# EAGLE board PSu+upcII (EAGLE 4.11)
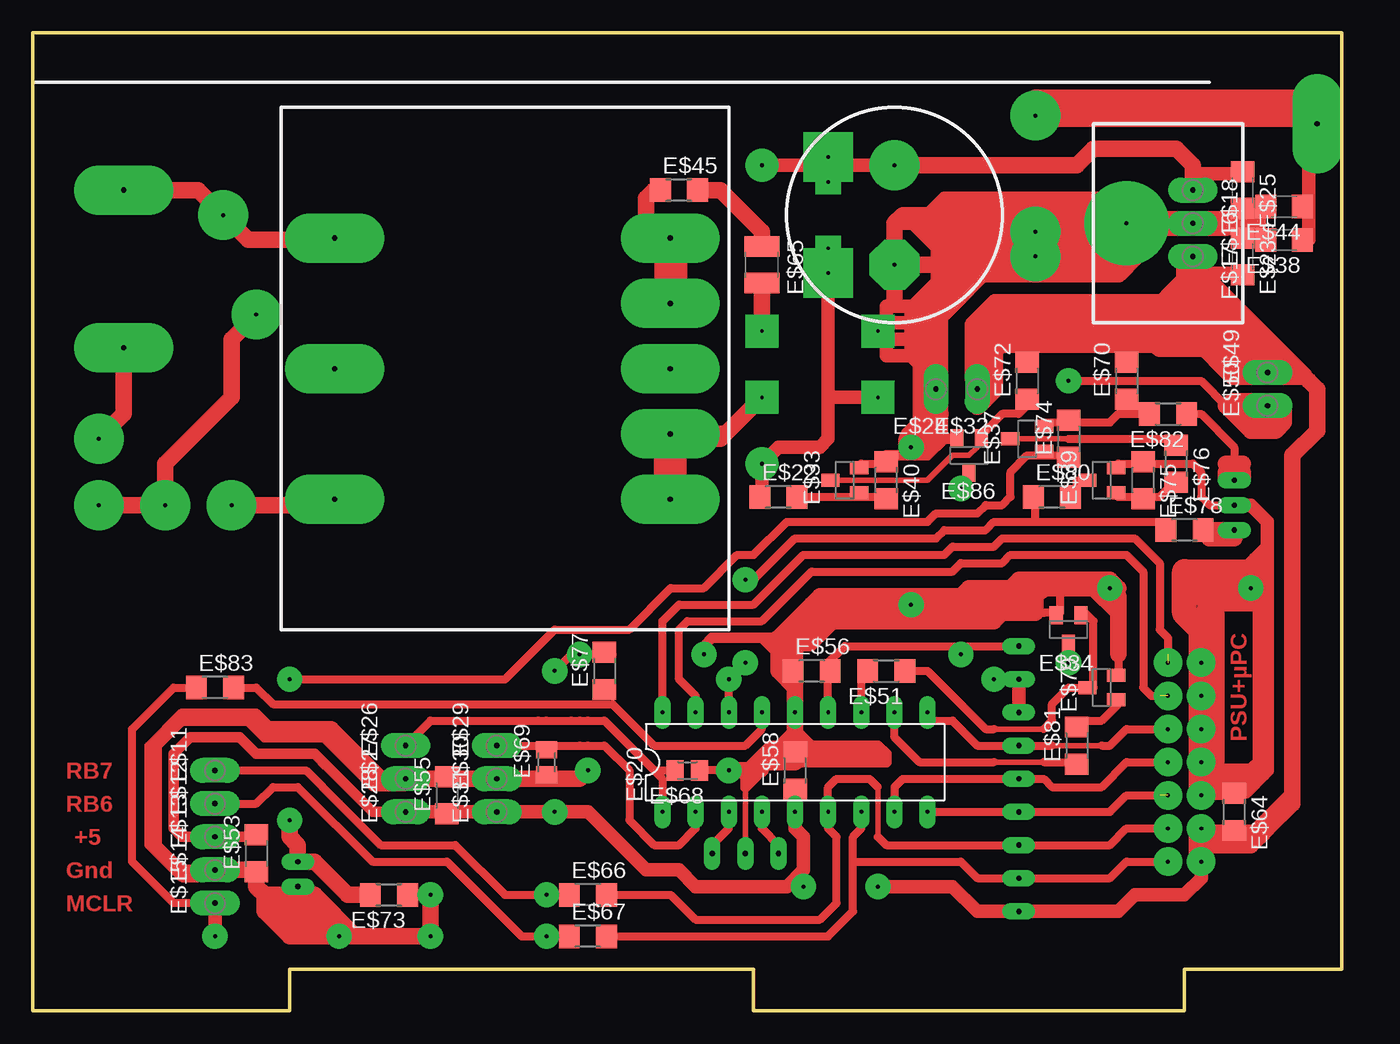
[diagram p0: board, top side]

Size 100.33 x 74.93 mm. Coordinates in mm from the lower left corner, seen from the top.
Outline: 0,0 19.68,0 19.68,3.17 55.24,3.17 55.24,0 88.27,0 88.27,3.17 100.33,3.17 100.33,74.93 0,74.93 0,0
Copper layers (1*16): Top 0.035mm / dielectric 1.5mm / Bottom 0.035mm
Design rules "default": minimum track width 10mil, minimum drill 24mil, track to track 8mil, track to pad 8mil, pad to pad 8mil, via to via 8mil, smd to smd 8mil, copper to edge 40mil, drill to drill 8mil, minimum pad ring 10mil, minimum via ring 8mil, stop-mask expansion 4mil, vias tented up to drill 0mil, thermal gap 10mil

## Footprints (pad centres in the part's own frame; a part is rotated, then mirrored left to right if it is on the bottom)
EC3,81 = drill 0.406 pad 3.81 long: P$1 0,0
P1-13Y = drill 0.406 pad 1.905 long: 1 0,0
DIL18 = drill 0.305 pad 1.27 long: 1 -10.16,-3.81; 2 -7.62,-3.81; 3 -5.08,-3.81; 4 -2.54,-3.81; 5 0,-3.81; 6 2.54,-3.81; 7 5.08,-3.81; 8 7.62,-3.81; 9 10.16,-3.81; 10 10.16,3.81; 11 7.62,3.81; 12 5.08,3.81; 13 2.54,3.81; 14 0,3.81; 15 -2.54,3.81; 16 -5.08,3.81; 17 -7.62,3.81; 18 -10.16,3.81
EC1,27 = drill 0.406 pad 1.27 long: P$1 0,0
R1206 = smd 1.6 x 1.803: 1 -1.422,0; 2 1.422,0
C1206 = smd 1.6 x 1.8: 1 -1.4,0; 2 1.4,0
SOT23 = smd 1 x 1.4: 1 -0.95,-1.1; 2 0.95,-1.1; 3 0,1.1
SOT23W = smd 1 x 1.4: 1 -0.95,-1.303; 3 0.95,-1.303; 4 0,1.303
C1210 = smd 1.6 x 2.7: 1 -1.4,0; 2 1.4,0
M0805 = smd 1.3 x 1.6: 1 -0.95,0; 2 0.95,0

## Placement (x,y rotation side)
E$1  [EC3,81]  23.14,59.19 90 top
E$2  [EC3,81]  6.99,50.8 90 top
E$3  [EC3,81]  23.14,39.19 90 top
E$4  [EC3,81]  6.99,62.87 90 top
E$5  [EC3,81]  48.85,59.19 90 top
E$6  [EC3,81]  48.85,54.19 90 top
E$7  [EC3,81]  48.85,49.19 90 top
E$8  [EC3,81]  48.85,44.19 90 top
E$9  [EC3,81]  48.85,39.19 90 top
E$10  [EC3,81]  23.14,49.19 90 top
E$11  [P1-13Y]  13.97,18.41 90 top
E$12  [P1-13Y]  13.97,15.88 90 top
E$13  [P1-13Y]  13.97,13.34 90 top
E$14  [P1-13Y]  13.97,10.79 90 top
E$15  [P1-13Y]  13.97,8.26 90 top
E$16  [P1-13Y]  88.9,60.33 270 top
E$17  [P1-13Y]  88.9,57.78 270 top
E$18  [P1-13Y]  88.9,62.87 270 top
E$19  [EC3,81]  98.42,67.94 0 top
E$20  [DIL18]  58.42,19.05 0 top
E$21  [EC1,27]  75.56,25.4 270 top
E$22  [R1206]  57.15,39.37 0 top
E$23  [C1206]  92.71,57.78 270 top
E$24  [P1-13Y]  69.22,47.62 180 top
E$25  [C1206]  92.71,62.87 270 top
E$26  [P1-13Y]  28.57,20.32 90 top
E$27  [P1-13Y]  28.57,17.78 90 top
E$28  [P1-13Y]  28.57,15.24 90 top
E$29  [P1-13Y]  35.56,20.32 90 top
E$30  [P1-13Y]  35.56,17.78 90 top
E$31  [P1-13Y]  35.56,15.24 90 top
E$32  [P1-13Y]  72.39,47.62 180 top
E$33  [SOT23]  62.23,40.64 90 top
E$34  [SOT23]  79.38,29.21 180 top
E$35  [EC1,27]  20.32,9.53 270 top
E$36  [EC1,27]  20.32,11.43 270 top
E$37  [SOT23W]  76.2,43.81 90 top
E$38  [C1206]  95.89,59.05 180 top
E$39  [SOT23]  81.92,40.64 90 top
E$40  [R1206]  65.41,40.64 270 top
E$41  [EC1,27]  57.15,12.06 180 top
E$42  [EC1,27]  54.61,12.06 180 top
E$43  [EC1,27]  52.07,12.06 180 top
E$44  [C1206]  95.89,61.59 180 top
E$45  [R1206]  49.53,62.87 0 top
E$46  [EC1,27]  92.08,36.83 90 top
E$47  [EC1,27]  92.08,38.73 90 top
E$48  [EC1,27]  92.08,40.64 90 top
E$49  [P1-13Y]  94.61,48.9 90 top
E$50  [P1-13Y]  94.61,46.35 90 top
E$51  [R1206]  65.41,26.04 180 top
E$52  [EC1,27]  75.56,22.86 270 top
E$53  [R1206]  17.14,12.06 90 top
E$54  [EC1,27]  75.56,20.32 270 top
E$55  [R1206]  31.75,16.51 90 top
E$56  [R1206]  59.69,26.04 0 top
E$57  [EC1,27]  75.56,17.78 270 top
E$58  [R1206]  58.42,18.41 90 top
E$59  [EC1,27]  75.56,15.24 270 top
E$60  [EC1,27]  75.56,12.7 270 top
E$61  [EC1,27]  75.56,10.16 270 top
E$62  [EC1,27]  75.56,27.94 270 top
E$63  [EC1,27]  75.56,7.62 270 top
E$64  [R1206]  92.08,15.24 270 top
E$65  [C1210]  55.88,57.15 270 top
E$66  [R1206]  42.55,8.89 0 top
E$67  [R1206]  42.55,5.71 0 top
E$68  [M0805]  50.16,18.41 180 top
E$69  [M0805]  39.37,19.05 90 top
E$70  [R1206]  83.82,48.26 90 top
E$72  [R1206]  76.2,48.26 90 top
E$73  [R1206]  27.3,8.89 180 top
E$74  [R1206]  79.38,43.81 90 top
E$75  [R1206]  85.09,40.64 270 top
E$76  [R1206]  87.63,41.91 270 top
E$77  [R1206]  43.81,26.04 90 top
E$78  [R1206]  88.27,36.83 0 top
E$79  [SOT23]  81.92,24.77 90 top
E$80  [R1206]  78.11,39.37 0 top
E$81  [R1206]  80.01,20.32 90 top
E$82  [R1206]  87,45.72 180 top
E$83  [R1206]  13.97,24.77 0 top
E$86  [SOT23W]  71.75,42.55 180 top

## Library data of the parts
E$1-E$10 E$19 E$21 E$35 E$36 E$41-E$43 E$46-E$48 E$52 E$54 E$57 E$59-E$63 = Pads
E$11-E$18 E$24 E$26-E$32 E$49 E$50 = testpad
E$20 = 40xx
E$22 E$23 E$25 E$37 E$38 E$40 E$44 E$45 E$51 E$53 E$55 E$56 E$58 E$64-E$70 E$72-E$78 E$80-E$83 E$86 = smd-ipc
E$33 E$34 E$39 E$79 = transistor-npn

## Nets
S$2: E$2.P$1 E$4.P$1
S$5: E$13.1 E$20.5 E$28.1 E$31.1
S$6: E$18.1
S$25: E$20.7
S$26: E$20.6
S$27: E$20.12
S$29: E$50.1
S$32: E$20.17
S$33: E$20.4
S$34: E$20.3
S$36: E$36.P$1
S$40: E$11.1
S$44: E$17.1 E$49.1
S$45: E$20.2 E$29.1
S$50: E$21.P$1 E$52.P$1
S$54: E$47.P$1
S$57: E$20.13
S$60: E$20.14
S$65: E$12.1
S$66: E$27.1 E$30.1
S$68: E$20.16
S$71: E$20.1 E$26.1
S$75: E$14.1
S$80: E$20.11
S$85: E$48.P$1
S$87: E$15.1
S$88: E$16.1
S$91: E$20.15
S$101: E$46.P$1
S$102: E$20.9

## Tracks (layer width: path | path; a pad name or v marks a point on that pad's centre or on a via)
S$1  (via drill 0.3 pad 3.81)
  Top 1.27: v15.24,38.73 22.86,38.73
S$2  (via drill 0.3 pad 3.81)
  Top 1.27: E$4.P$1 12.7,62.87 v14.61,60.96 16.51,59.05 23.5,59.05 | v5.08,43.81 6.99,45.72 E$2.P$1 | v5.08,38.73 v10.16,38.73 10.16,41.91 15.24,46.99 15.24,51.44 v17.14,53.34
S$3
  Top 0.61: 16.51,22.86 17.78,21.59 18.41,20.95 | 16.51,22.86 11.43,22.86 8.89,20.32 8.89,12.7 11.43,10.16 12.7,10.16 | 16.51,22.86 17.14,22.86 18.41,21.59
  Top 1.27: 27.3,17.78 26.67,17.78 22.86,21.59 18.41,21.59 17.78,21.59
S$4
  Top 1.27: 66.04,54.61 66.04,55.88
S$5
  Top 0.61: E$31.1 41.27,15.24
  Top 0.813: E$31.1 E$28.1 26.04,15.24 22.86,18.41 | 22.86,18.41 22.23,19.05 | 22.86,18.41 21.59,19.68 17.14,19.68 15.88,20.95 12.06,20.95 10.79,19.68 10.79,13.97 11.43,13.34 E$13.1 17.14,13.34
  Top 1.016: E$20.5 58.42,13.97 59.05,13.34 59.05,10.79 57.78,9.53 50.8,9.53 49.53,10.79 46.99,10.79 42.55,15.24 41.27,15.24 | 41.27,15.24 41.91,15.24 | E$28.1 41.27,15.24
S$6  (via drill 0.25 pad 3.81, 0.3 pad 2.54, 0.3 pad 3.81)
  Top 1.016: v60.96,65.41 62.87,64.77 | v55.88,64.77 62.87,64.77 | 62.87,64.77 v66.04,64.77
  Top 1.27: E$18.1 88.9,64.77 87.63,66.04 81.28,66.04 80.01,64.77 v66.04,64.77
S$7
  Top 0.61: 35.56,20.32 36.83,20.32
S$8  (via drill 0.3 pad 1.93)
  other vias: 59.05,9.53
S$9  (via drill 0.25 pad 3.81, 0.3 pad 2.54)
  Top 0.813: 60.33,43.18 58.42,43.18 | 62.23,46.99 64.77,46.99 65.41,46.99
  Top 1.016: 55.88,39.37 v55.88,41.91 57.15,43.18 60.33,43.18 60.96,43.81 60.96,46.99 | 64.77,46.99 60.96,46.99 | 60.96,46.99 v60.96,56.52
S$10  (via drill 0.3 pad 1.93)
  Top 0.61: v54.61,33.02 55.24,33.02 58.42,36.2 69.22,36.2 69.85,36.83 73.03,36.83 73.66,37.47 76.83,37.47 | 76.83,37.47 87,37.47 | 76.83,37.47 76.83,38.73
S$11  (via drill 0.3 pad 1.93, 0.3 pad 2.18)
  Top 1.016: 90.81,32.38 90.81,33.02 | 90.81,32.38 v93.34,32.38 | 90.81,31.75 90.81,32.38 | 90.81,31.75 93.34,31.75 | 90.81,18.41 90.81,17.78 | 90.81,18.41 90.81,31.75 | 93.98,18.41 90.81,18.41
  Top 1.93: 93.98,34.29 93.34,33.66 88.27,33.66 88.27,30.48 89.53,29.21 v89.53,26.67 89.53,17.14 | 93.98,18.41 92.71,17.14 89.53,17.14 | v89.53,16.51 89.53,17.14
S$12
  Top 2.54: 83.82,59.69 76.83,59.69 74.3,57.15
S$13  (via drill 0.25 pad 1.93)
  other vias: 60.96,63.5
S$14
  Top 0.61: 41.27,22.23 42.55,22.23
S$15  (via drill 0.25 pad 1.93)
  other vias: 60.96,58.42
S$16
  Top 0.61: 58.42,39.37 64.77,39.37
S$17  (via drill 0.3 pad 1.93)
  other vias: 40.01,15.24
S$18
  Top 0.61: 63.5,41.91 64.77,41.91
S$19  (via drill 0.3 pad 1.93)
  other vias: 73.66,25.4
S$20
  Top 1.422: 76.83,69.85 98.42,69.85
S$21
  Top 2.54: 48.9,39.37 48.9,43.81
S$22
  Top 1.016: 89.53,64.14 92.71,64.14
S$23  (via drill 0.3 pad 1.93)
  other vias: 71.12,27.3
S$24
  Top 0.61: 83.19,39.37 86.36,39.37 87,40.01
S$25  (via drill 0.3 pad 2.18)
  Top 0.61: v87,11.43 83.82,11.43 82.55,10.16 72.39,10.16 71.12,11.43 62.87,11.43 | E$20.7 63.5,13.97 62.87,13.34 62.87,11.43 | 62.87,11.43 62.87,7.62 60.96,5.71 44.45,5.71
S$26  (via drill 0.3 pad 2.18)
  Top 0.406: 64.77,17.14 64.77,13.34
  Top 0.61: 43.81,8.89 48.9,8.89 50.8,6.99 60.33,6.99 61.59,8.26 61.59,13.34 60.96,13.97 E$20.6 60.96,17.14 61.59,17.78 64.14,17.78 64.77,17.14 | v87,13.97 83.82,13.97 82.55,12.7 65.41,12.7 64.77,13.34
S$27
  Top 0.61: 63.5,24.77 E$20.12 63.5,26.04
S$28
  Top 1.27: 75.56,52.07 76.2,52.07
S$29  (via drill 0.3 pad 1.93)
  Top 0.61: v79.38,48.26 89.53,48.26 91.44,46.35 92.08,46.35
  Top 1.27: 95.89,46.35 95.89,45.09 95.25,44.45 93.34,44.45 91.44,46.35
  Top 1.93: E$50.1 92.71,46.35 | 92.71,46.35 92.08,46.35 | 92.71,46.35 92.71,45.72 93.34,45.09 95.25,45.09 95.25,46.35
S$31  (via drill 0.3 pad 1.93)
  other vias: 71.12,40.01
S$32  (via drill 0.3 pad 2.18)  (1 unrouted)
  Top 0.61: E$20.17 50.8,24.13 49.53,25.4 49.53,29.21 50.16,29.84 55.88,29.84 59.69,33.66 70.48,33.66 71.12,34.29 74.3,34.29 74.93,34.92 83.82,34.92 85.09,33.66 85.09,24.77 85.72,24.13 v87,24.13 | 86.36,24.13 87,24.77
S$33
  Top 0.61: E$20.4 55.88,13.97 57.15,12.7
S$34
  Top 0.61: E$20.3 53.34,13.97 52.07,12.7
S$35
  Top 2.54: 48.9,59.05 48.9,53.98
S$36  (via drill 0.3 pad 1.93)
  Top 0.61: 25.4,8.89 26.04,8.89
  Top 1.27: v19.68,14.61 19.68,13.34 20.32,12.7 E$36.P$1 21.59,11.43 24.13,8.89 25.4,8.89
S$37  (via drill 0.3 pad 2.18)  (1 unrouted)
  Top 0.61: 48.26,23.5 48.26,29.84 49.53,31.11 55.24,31.11 59.05,34.92 69.85,34.92 70.48,35.56 73.66,35.56 74.3,36.2 84.45,36.2 86.36,34.29 86.36,29.21 87,28.57 87,27.3
  other vias: 87,26.67
S$38  (via drill 0.3 pad 1.93)
  Top 0.61: v40.01,26.04 41.27,27.3 v41.91,27.3 | v41.91,27.3 43.18,27.3 | v41.91,27.3 44.45,27.3
S$39  (via drill 0.3 pad 1.93)
  other vias: 79.38,26.67
S$40  (via drill 0.3 pad 1.93)
  Top 0.61: 23.5,15.88 22.23,17.14 | 23.5,15.88 26.67,12.7 32.38,12.7 36.2,8.89 v39.37,8.89 | 23.5,15.88 20.95,18.41 E$11.1 | v39.37,8.89 41.27,8.89 | v39.37,8.89 38.73,8.89
S$41  (via drill 0.25 pad 2.54)
  Top 1.016: 52.07,43.81 52.7,43.81 | 55.24,46.35 v55.88,46.99
  Top 1.27: 49.53,43.81 52.7,43.81 55.24,46.35
S$42
  Top 0.813: 59.05,19.68 64.77,19.68
S$43
  Top 0.406: 54.61,13.97 54.61,16.51
S$44  (via drill 0.3 pad 1.93, 0.3 pad 2.18)
  Top 0.406: 97.79,48.9 90.17,56.52
  Top 0.61: 71.75,48.26 71.75,52.7 73.66,54.61 87,54.61 | 76.2,52.07 76.2,50.8 | 83.82,51.44 83.82,49.53 | 96.52,48.26 97.79,48.26
  Top 0.813: 85.72,50.8 85.09,50.8 | 85.09,50.8 83.19,50.8 82.55,51.44 | 74.93,51.44 78.11,51.44 | 85.09,50.8 76.2,50.8 | 76.2,50.8 74.3,50.8 73.66,50.16 | 76.2,49.53 76.2,50.8
  Top 1.016: 87.63,53.34 91.44,53.34 | 90.17,53.98 90.81,53.98 | 90.17,53.98 89.53,54.61 91.44,54.61 89.53,56.52 90.17,56.52 92.71,56.52 | 90.17,53.98 88.9,53.98 | v89.53,11.43 89.53,10.16 88.27,8.89 84.45,8.89 83.19,7.62 72.39,7.62 70.48,9.53 v64.77,9.53
  Top 1.27: 88.9,55.88 E$17.1 88.9,55.24 88.27,54.61 | 88.27,54.61 88.27,55.88 88.27,57.78 | 88.27,54.61 87.63,53.98 83.19,53.98 | 83.19,53.98 82.55,53.98 | 78.74,53.98 83.19,53.98 | 78.74,53.98 75.56,53.98 74.93,53.34 | 74.93,53.34 73.66,52.07 | 78.74,53.98 76.83,52.07 76.83,53.34 | 76.83,53.34 74.93,53.34 | 78.11,53.34 77.47,52.7 | 78.74,53.98 78.11,53.34 | 77.47,53.34 78.11,53.34 | 76.83,53.34 77.47,53.34 | 87.63,53.34 88.9,54.61 | 87.63,53.34 77.47,53.34 | 87.63,53.34 88.27,53.34 88.9,53.98 89.53,54.61 89.53,55.24 89.53,56.52 89.53,57.15 | 96.52,48.9 97.16,48.9 97.79,48.26 98.42,47.62 98.42,44.45 96.52,42.55 96.52,16.51 | 90.17,12.7 93.34,12.7 94.61,13.97 | 94.61,13.97 93.98,13.34 | 94.61,13.97 96.52,15.88 96.52,16.51 | 93.34,13.34 96.52,16.51
  Top 1.422: 77.47,52.07 76.83,52.07 | 92.08,52.07 77.47,52.07 | 92.08,50.8 86.36,50.8 85.72,51.44 83.82,51.44 82.55,51.44 78.11,51.44 77.47,52.07 | 77.47,52.07 76.2,52.07 74.93,52.07 73.66,50.8 | 73.66,50.8 72.39,49.53 | 72.39,49.53 72.39,48.26 | 72.39,49.53 72.39,52.7 73.66,53.98 86.36,53.98 87,54.61 88.27,55.88 | 73.66,50.8 73.03,51.44 73.03,52.07 73.66,52.7 | 72.39,46.35 73.66,47.62 73.66,50.16 73.66,50.8
  Top 1.93: 90.17,53.98 92.08,52.07 92.08,50.8 92.08,48.9 | 92.08,48.9 E$49.1 96.52,48.9 95.25,50.16 | 89.53,13.34 v89.53,13.97 | 89.53,13.34 93.34,13.34 | v89.53,11.43 89.53,13.34 | 95.25,50.16 91.44,53.98 90.81,53.98 89.53,55.24 | 95.25,50.16 95.25,49.53 93.98,49.53 93.34,50.16 | 92.08,48.9 89.53,51.44
S$45
  Top 0.61: E$20.2 50.8,13.97 49.53,12.7 47.62,12.7 45.72,14.61 45.72,18.41 43.81,20.32 41.91,20.32 | E$29.1 41.91,20.32 | 41.91,20.32 42.55,20.32
  Top 0.813: E$20.2 50.8,14.61
S$46  (via drill 0.3 pad 1.93, 0.3 pad 3.81)
  Top 0.61: 69.85,43.81 69.85,45.72
  Top 0.813: 66.67,42.55 v67.31,43.18 68.58,43.18 | 65.41,42.55 66.67,42.55 | 69.85,43.81 69.22,43.81 | 69.85,43.81 70.48,43.81 | 67.31,43.81 69.22,43.81 | 69.22,43.81 69.22,44.45 | 66.67,42.55 68.58,42.55 69.85,43.81 | 67.31,60.33 69.22,58.42 69.22,55.88 67.31,53.98
  Top 1.016: 67.94,60.33 69.85,58.42 69.85,57.78 | 69.85,57.15 69.85,57.78 | 69.85,57.15 69.85,55.88 67.94,53.98 67.31,53.98 65.41,53.98 65.41,52.7 67.31,52.7 | 66.04,60.33 67.31,60.33 67.94,60.33 | 69.85,57.15 v66.04,57.15 | 67.31,51.44 65.41,51.44 65.41,50.16 67.31,50.16 | 67.31,51.44 68.58,50.16 67.94,50.16 | 67.94,51.44 67.31,51.44 | 67.94,51.44 68.58,51.44 | 67.31,52.7 67.31,53.34 67.94,53.34 | 67.31,51.44 67.31,52.7 | 67.94,53.34 67.94,51.44 | 69.22,53.34 67.94,53.34 | 67.31,50.16 67.94,50.16 | 67.31,51.44 67.31,50.16 | 67.31,50.16 68.58,48.9 | 67.94,50.16 67.94,45.09 | 69.22,60.33 67.94,60.33 | 69.85,60.33 69.22,60.33 | 69.85,57.78 69.85,60.33 | 69.22,60.33 69.22,59.69 | 69.85,60.33 70.48,60.33 70.48,57.15 70.48,56.52 70.48,55.24 | 66.67,60.96 68.58,60.96 69.85,62.23 83.82,62.23
  Top 1.27: 70.48,57.15 v66.04,57.15 66.04,60.33 66.67,60.96 69.85,60.96
  Top 1.422: 69.22,53.34 69.22,53.98 74.93,59.69 | 70.48,56.52 75.56,61.59 70.48,61.59 69.85,60.96 73.66,60.96 71.12,58.42 71.12,59.69 71.75,60.33
  Top 1.93: 69.22,53.34 69.22,45.72 67.31,43.81 v67.31,43.18
S$47
  Top 0.406: 60.96,40.64 68.58,40.64 70.48,42.55 71.75,42.55 72.39,43.18 72.39,43.81 73.03,44.45
  Top 0.61: 76.2,46.99 76.2,46.35 75.56,45.72 74.3,45.72 73.03,44.45
S$48  (via drill 0.25 pad 2.54)
  other vias: 64.77,52.07
S$49
  Top 1.27: 46.99,60.33 46.99,62.23 47.62,62.87
S$50
  Top 1.016: E$52.P$1 E$21.P$1
S$51
  Top 1.27: 91.44,41.91 92.71,41.91
S$52  (via drill 0.3 pad 2.18)
  Top 0.61: v89.53,24.13 90.17,24.13
S$53
  Top 1.27: 51.44,62.87 52.7,62.87 55.88,59.69 55.88,59.05
S$54
  Top 0.61: 83.19,41.91 88.9,41.91 89.53,41.27 89.53,39.37 90.17,38.73 E$47.P$1
  Top 1.016: E$47.P$1 93.34,38.73 94.61,37.47 94.61,35.56 | 94.61,35.56 93.98,34.92 | 94.61,33.02 93.98,32.38 | 94.61,33.02 94.61,35.56 | 94.61,18.41 94.61,33.02
S$55
  Top 0.61: 85.72,45.72 83.19,45.72 82.55,45.09 77.47,45.09
S$56  (via drill 0.3 pad 1.93)
  other vias: 67.31,31.11
S$57
  Top 0.61: 74.93,27.94 62.23,27.94 60.96,26.67 E$20.13
S$58  (via drill 0.3 pad 3.81)
  other vias: 76.83,68.58
S$59
  Top 0.61: 80.01,40.01 80.01,40.64
S$60  (via drill 0.3 pad 1.93)
  Top 0.406: 54.61,13.34 54.61,17.14
  Top 0.61: 83.19,27.3 83.19,26.04 | v53.34,18.41 50.8,18.41
  Top 0.813: v51.44,27.3 51.44,27.94 52.07,28.57 55.88,28.57 | 57.78,28.57 57.15,28.57 55.88,28.57 | 55.88,19.68 56.52,20.32 57.15,20.32 58.42,21.59 59.69,20.32 64.77,20.32 65.41,19.68 65.41,19.05 57.78,19.05 58.42,19.68 | 55.88,19.68 57.78,19.68 | 54.61,18.41 55.88,19.68 | 58.42,20.95 58.42,20.32 | 55.88,18.41 56.52,19.05 54.61,17.14 54.61,17.78 | 55.88,28.57 57.15,27.3 | 59.05,27.94 59.69,27.94 61.59,29.84
  Top 1.016: 55.88,18.41 55.24,18.41
  Top 1.27: 83.19,30.48 83.19,27.3 | 83.19,30.48 83.19,31.11 | 83.19,31.75 83.19,30.48 | 83.19,31.75 v82.55,32.38 81.28,32.38 | 83.19,32.38 82.55,33.02 81.92,33.02 | 76.83,31.11 76.83,30.48 76.2,30.48 | 81.92,33.02 83.19,31.75 | 76.83,31.11 76.83,31.75 77.47,32.38 | 81.28,32.38 83.19,30.48 | 77.47,32.38 81.28,32.38 | 81.92,33.02 75.56,33.02 74.93,32.38 | 76.2,30.48 76.83,31.11 | 76.2,30.48 74.3,30.48 73.66,29.84 71.12,29.84 | 74.93,32.38 77.47,32.38 | 74.93,32.38 71.75,32.38 71.12,31.75 60.33,31.75 | 71.12,29.84 71.75,29.84 | 60.33,31.75 59.69,31.11 | 60.33,29.84 61.59,29.84 71.12,29.84 | 60.33,29.84 59.05,29.84 58.42,29.21 58.42,27.94 | 58.42,27.94 60.33,29.84 | 57.15,28.57 60.33,31.75 | 58.42,27.3 57.15,28.57 | 58.42,27.3 58.42,27.94 | 57.15,28.57 57.15,27.3 57.15,26.04 58.42,24.77 | 58.42,24.77 58.42,27.3 | 58.42,24.77 E$20.14 58.42,21.59 58.42,20.95 58.42,19.68 | v53.34,18.41 54.61,18.41 55.24,18.41 | 58.42,19.05 57.78,19.05 56.52,19.05 55.88,19.05
S$61
  Top 0.813: 88.27,52.7 90.17,52.7
S$62
  Top 1.422: 84.45,57.78 85.09,58.42 | 84.45,57.78 83.19,56.52 72.39,56.52 | 75.56,57.78 84.45,57.78
  Top 1.93: 75.56,57.78 76.83,59.05
S$64
  Top 1.27: 19.05,8.26 20.95,8.26 22.86,6.35 20.95,6.35 20.95,6.99 20.32,7.62
S$65  (via drill 0.3 pad 1.93)
  Top 0.61: v39.37,5.71 41.27,5.71 | v39.37,5.71 39.37,6.35 | v39.37,5.71 38.73,5.71 | v39.37,5.71 37.47,5.71 31.75,11.43 26.04,11.43 20.32,17.14 18.41,17.14 17.14,15.88 E$12.1
S$66
  Top 0.813: 33.02,17.78 E$30.1
  Top 1.27: 42.55,18.41 41.91,17.78 33.02,17.78 E$27.1
S$67  (via drill 0.3 pad 3.81)
  other vias: 76.83,57.78
S$68  (via drill 0.3 pad 1.93)
  Top 0.61: E$20.16 v53.34,25.4 v54.61,26.67
S$70  (via drill 0.3 pad 2.18)
  Top 0.61: 66.04,15.88 66.04,17.14 66.67,17.78 77.47,17.78 78.11,17.14 81.92,17.14 83.82,19.05 v87,19.05
S$71
  Top 0.61: 38.73,22.23 39.37,22.23 | 38.73,22.23 41.91,22.23 | 41.91,22.23 42.55,22.23 | 38.73,22.23 30.48,22.23 E$26.1 | 41.91,22.23 43.81,22.23 47.62,18.41 | 47.62,18.41 48.26,17.78 48.26,15.88 | 48.26,15.88 E$20.1 | 48.26,15.88 48.26,16.51 | 47.62,18.41 48.9,18.41
S$72
  Top 0.61: 80.64,22.23 81.92,22.23 83.19,23.5
S$73
  Top 1.016: 92.08,60.33 93.98,60.33
S$74
  Top 0.406: 74.93,43.81 79.38,43.81
  Top 0.61: 79.38,43.81 87.63,43.81
S$75  (via drill 0.3 pad 1.93)
  Top 0.61: v30.48,8.89 29.21,8.89 | 22.86,20.95 26.67,17.14 | 26.67,17.14 28.57,17.14 | 26.67,17.14 26.04,17.14 22.23,20.95
  Top 0.813: E$14.1 11.43,10.79 9.53,12.7 9.53,20.32 11.43,22.23 16.51,22.23 17.78,20.95 22.23,20.95 22.86,20.95
  Top 1.27: v30.48,8.89 v30.48,5.71 24.77,5.71 | v23.5,5.71 24.77,5.71 | 21.59,8.89 v23.5,5.71 | 20.95,5.71 v23.5,5.71 | 20.95,5.71 19.68,5.71 17.78,7.62 17.78,8.89 | 17.78,8.89 20.95,5.71 | 17.78,8.89 21.59,8.89 | 17.78,8.89 17.14,9.53 17.14,10.79 E$14.1 | 21.59,8.89 24.77,5.71
S$76  (via drill 0.3 pad 1.93)
  Top 0.61: v19.68,25.4 36.2,25.4 40.01,29.21 45.72,29.21 48.9,32.38 51.44,32.38 53.98,34.92 55.24,34.92 57.78,37.47 68.58,37.47 69.22,38.1 72.39,38.1 73.03,38.73 74.3,38.73 74.93,39.37 74.93,41.27 76.2,42.55 79.38,42.55
S$78
  Top 0.406: 73.66,21.59 77.47,21.59
  Top 0.61: 80.64,24.77 79.38,24.77 78.11,23.5 78.11,22.23 77.47,21.59 | 73.66,21.59 73.03,21.59 71.12,23.5 | 71.12,23.5 70.48,24.13 | 71.12,23.5 68.58,26.04 66.67,26.04
S$79
  Top 1.422: 60.33,30.48 73.66,30.48
S$80
  Top 0.406: 73.66,19.05 77.47,19.05
  Top 0.61: 66.04,22.23 E$20.11 66.04,20.95 67.94,19.05 73.66,19.05 | 77.47,19.05 79.38,19.05
S$81
  Top 1.27: 74.93,52.07 74.93,52.7
S$82  (via drill 0.25 pad 2.54)
  other vias: 64.77,46.99
S$83
  Top 1.016: 93.34,59.69 93.98,59.69 93.98,60.96 93.34,60.96
S$84
  Top 0.61: 80.64,30.48 81.28,29.84 81.28,24.77
S$85
  Top 0.61: 91.44,41.27 E$48.P$1 92.08,43.18 89.53,45.72 88.27,45.72
  Top 1.27: 92.71,40.64 92.71,41.27 91.44,41.27 91.44,40.64 E$48.P$1 92.71,40.64
S$86  (via drill 0.3 pad 1.93)
  other vias: 42.55,18.41
S$87  (via drill 0.3 pad 1.93)
  Top 0.61: 12.06,24.77 10.79,24.77 7.62,21.59 7.62,11.43 10.79,8.26 E$15.1
  Top 1.016: v13.97,5.71 E$15.1
S$88  (via drill 0.3 pad 6.45)
  Top 1.016: 69.85,53.34 73.66,57.15
  Top 1.93: 91.44,60.33 E$16.1 v83.82,60.33
  Top 2.54: 73.66,57.15 76.83,60.33 v83.82,60.33 | 83.82,60.96 76.83,60.96 74.93,59.05
  Top 3.81: v83.82,60.33 83.82,60.96
S$89
  Top 1.422: 70.48,31.11 76.2,31.11
S$90
  Top 0.61: 78.11,30.48 77.47,30.48
S$91
  Top 0.61: 15.88,24.77 17.14,24.77 18.41,23.5 44.45,23.5 47.62,20.32 54.61,20.32 55.88,21.59 E$20.15 55.88,22.23
S$92
  Top 1.016: 97.79,59.05 97.79,66.04
S$93  (via drill 0.25 pad 2.54)
  Top 0.813: 55.88,55.24 55.88,55.88
  Top 1.27: v55.88,52.07 55.88,55.24
S$97
  Top 0.813: 52.07,44.45 53.34,44.45
S$99  (via drill 0.3 pad 3.81)
  other vias: 76.83,59.69
S$101
  Top 1.27: E$46.P$1 89.53,36.83 90.17,36.2 92.08,36.2
S$102  (via drill 0.3 pad 2.18)  (1 unrouted)
  Top 0.61: 86.36,16.51 83.82,16.51 82.55,15.24 E$20.9
  other vias: 87,16.51
S$103  (via drill 0.3 pad 2.18)
  Top 0.406: 78.11,20.32 81.92,20.32
  Top 0.61: 81.92,20.32 82.55,20.32 83.82,21.59 v87,21.59 | 78.11,20.32 72.39,20.32 70.48,22.23 68.58,22.23
S$106
  Top 1.676: 76.83,68.58 97.79,68.58
S$107
  Top 0.61: 78.74,30.48 78.74,31.75
S$108  (via drill 0.3 pad 2.18)
  other vias: 89.53,21.59
S$109  (via drill 0.3 pad 2.18)
  other vias: 89.53,19.05
S$110
  Top 1.016: 93.98,19.05 93.98,31.11 | 93.98,31.11 93.98,33.02 | 93.98,31.11 90.17,31.11
  Top 1.93: 90.17,29.21 90.17,31.11 90.17,32.38 89.53,33.02

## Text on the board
Top: PSU+µPC | RB7 | RB6 | +5 | Gnd | MCLR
